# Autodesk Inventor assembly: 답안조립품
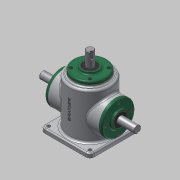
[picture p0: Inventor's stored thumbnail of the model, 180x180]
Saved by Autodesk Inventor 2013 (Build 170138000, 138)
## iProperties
Created: 2015-10
Part Number: 답안조립품
Document SubType Name: Assembly
Designer: Administrator
Author: Administrator
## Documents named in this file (14)
- C:\Users\Administrator\Desktop\451008V1002\답안조립품.iam
- C:\Users\Administrator\Desktop\451008V1002\본체.ipt
- C:\Users\Administrator\Desktop\451008V1002\M4.ipt
- C:\Users\Administrator\Desktop\451008V1002\메인 베벨기어.ipt
- C:\Users\Administrator\Desktop\451008V1002\메인 축.ipt
- 메인 축.ipt
- C:\Users\Administrator\Desktop\451008V1002\베어링 6203.ipt
- C:\Users\Administrator\Desktop\451008V1002\서브 베벨기어.ipt
- C:\Users\Administrator\Desktop\451008V1002\서브 축.ipt
- 서브 축.ipt
- C:\Users\Administrator\Desktop\451008V1002\오일실.ipt
- C:\Users\Administrator\Desktop\451008V1002\커버.ipt
- C:\Users\Administrator\Desktop\451008V1002\키 4x4.ipt
- C:\Users\Administrator\Desktop\451008V1002\키 5x5.ipt
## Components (12 placed, 1 different names)
1. M4:1
2. M4:2
3. M4:3
4. M4:4
5. M4:5
6. M4:6
7. M4:7
8. M4:8
9. M4:9
10. M4:10
11. M4:11
12. M4:12
